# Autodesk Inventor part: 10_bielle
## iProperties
Created: 2002-11
Part Number: 10_bielle
Material: Acier inoxydable - 440C
Document SubType Name: Modélisation
Designer: FIEVET
Control State: 0
Master: False
Checked Out: False
Shininess: 31.0
Length Units: 11269
Angle Units: 11279
Time Units: 11290
Mass Units: 11283
Length Display Precision: 3
Angle Display Precision: 2
Compacted: True
Density: 7.75
Volumn: 0.41484524202348483
Area: 5.921403849397006
PropertySet Name: Model Information
Author: FIEVET
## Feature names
1. Extrusion1
2. Chanfrein1 [Chamfer]
